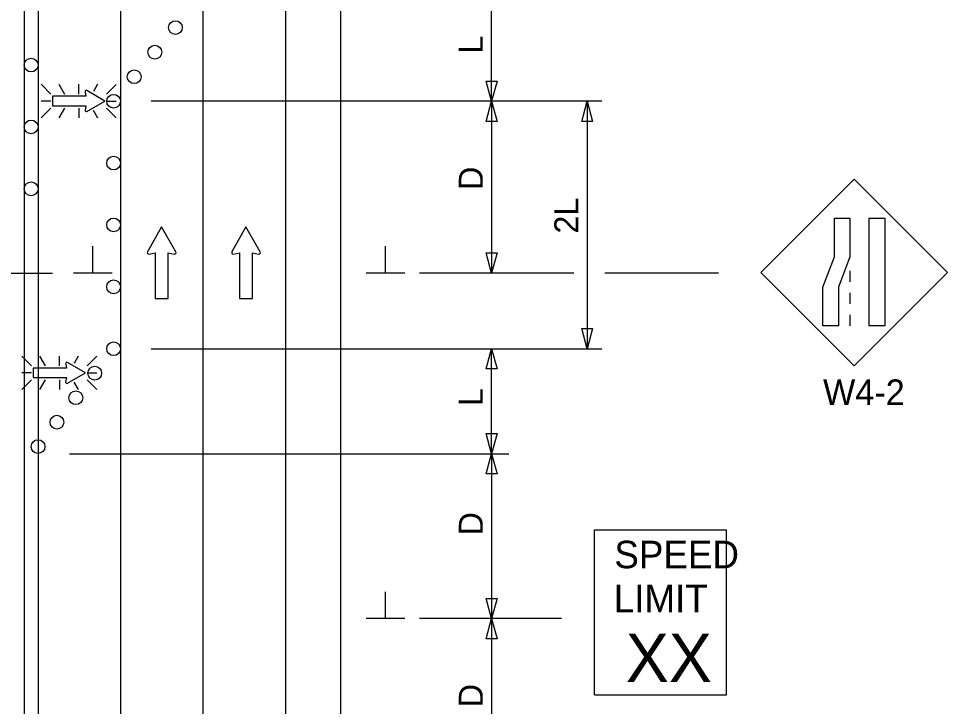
# Model space of a CAD drawing. Extents: x 16751 to 18475, y 5726 to 6923.
# Drawn here: x 17074.4 to 17344.7, y 6372.9 to 6573.1 of the extents above; entities that cross this region are included whole.
import ezdxf

# ---------------------------------------------------------------- set-up
doc = ezdxf.new("R2010")
doc.units = 0
for name, color, linetype in [('ALI_LEGAL_EX', 7, 'Continuous'), ('MT_SCRATCH_LEVEL_E', 7, 'Continuous'), ('PAVT_EDGE_EX', 7, 'Continuous'), ('TRAFFIC_SIGNS_PR', 7, 'Continuous'), ('TYPICAL_TEXT_DIMEN_PR', 7, 'Continuous')]:
    doc.layers.add(name, color=color, linetype=linetype)

msp = doc.modelspace()

# ---------------------------------------------------------------- linework, layer by layer
at = {"layer": 'ALI_LEGAL_EX'}
for p, q in [((17104.08, 6911.72), (17104.08, 6082.53)), ((17128.08, 6911.72), (17128.08, 6082.53)), ((17128.08, 6911.72), (17128.08, 6082.53))]:
    msp.add_line(p, q, dxfattribs=at)
for points in [[(17104.08, 6511.72), (17104.08, 6486.72)], [(17128.08, 6511.72), (17128.08, 6486.72)], [(17104.08, 6411.72), (17104.08, 6386.72)], [(17128.08, 6411.72), (17128.08, 6386.72)]]:
    msp.add_lwpolyline(points, dxfattribs=at)
at = {"layer": 'MT_SCRATCH_LEVEL_E'}
for p, q in [((17116.04, 6512.45), (17111.93, 6505.21)), ((17116.04, 6512.45), (17111.93, 6505.21)), ((17120.19, 6505.21), (17116.04, 6512.45)), ((17120.19, 6505.21), (17116.04, 6512.45)), ((17140.6, 6512.45), (17136.49, 6505.21)), ((17140.6, 6512.45), (17136.49, 6505.21)), ((17144.75, 6505.21), (17140.6, 6512.45)), ((17144.75, 6505.21), (17140.6, 6512.45)), ((17112.41, 6504.53), (17114.19, 6504.85)), ((17112.41, 6504.53), (17114.19, 6504.85)), ((17114.19, 6504.85), (17114.19, 6491.59)), ((17114.19, 6504.85), (17114.19, 6491.59)), ((17117.93, 6491.59), (17117.93, 6504.85)), ((17117.93, 6504.85), (17119.71, 6504.53)), ((17117.93, 6491.59), (17117.93, 6504.85)), ((17117.93, 6504.85), (17119.71, 6504.53)), ((17136.97, 6504.53), (17138.75, 6504.85)), ((17136.97, 6504.53), (17138.75, 6504.85)), ((17138.75, 6504.85), (17138.75, 6491.59)), ((17138.75, 6504.85), (17138.75, 6491.59)), ((17142.49, 6491.59), (17142.49, 6504.85)), ((17142.49, 6504.85), (17144.27, 6504.53)), ((17142.49, 6491.59), (17142.49, 6504.85)), ((17142.49, 6504.85), (17144.27, 6504.53)), ((17114.19, 6491.59), (17117.93, 6491.59)), ((17114.19, 6491.59), (17117.93, 6491.59)), ((17138.75, 6491.59), (17142.49, 6491.59)), ((17138.75, 6491.59), (17142.49, 6491.59))]:
    msp.add_line(p, q, dxfattribs=at)
for centre, start, end in [((17112.34, 6504.99), 150.4248, 279.9638), ((17112.34, 6504.99), 150.4248, 279.9638), ((17119.78, 6504.99), 260.0362, 29.7731), ((17119.78, 6504.99), 260.0362, 29.7731), ((17136.9, 6504.99), 150.4248, 279.9638), ((17136.9, 6504.99), 150.4248, 279.9638), ((17144.34, 6504.99), 260.0362, 29.7731), ((17144.34, 6504.99), 260.0362, 29.7731)]:
    msp.add_arc(centre, 0.463, start, end, dxfattribs=at)
at = {"layer": 'PAVT_EDGE_EX'}
for p, q in [((17076.08, 6911.72), (17076.08, 6082.53)), ((17080.08, 6911.72), (17080.08, 6082.53)), ((17152.08, 6911.72), (17152.08, 6082.53)), ((17168.08, 6911.72), (17168.08, 6082.53))]:
    msp.add_line(p, q, dxfattribs=at)
at = {"layer": 'TRAFFIC_SIGNS_PR'}
for p, q in [((17083.85, 6551.11), (17081.03, 6553.93)), ((17086.15, 6553.93), (17087.78, 6551.11)), ((17091.94, 6551.11), (17091.94, 6553.93)), ((17097.4, 6553.93), (17096.2, 6551.83)), ((17102.84, 6553.92), (17100.02, 6551.11)), ((17083.85, 6549.07), (17081.03, 6549.07)), ((17100.02, 6549.07), (17102.84, 6549.07)), ((17083.85, 6547.04), (17081.03, 6544.22)), ((17087.8, 6547.04), (17086.17, 6544.22)), ((17091.94, 6547.04), (17091.94, 6544.22)), ((17096.12, 6546.41), (17097.38, 6544.22)), ((17102.84, 6544.22), (17100.02, 6547.04)), ((17317.56, 6526.35), (17290.41, 6499.2)), ((17344.71, 6499.2), (17317.56, 6526.35)), ((17290.41, 6499.2), (17317.56, 6472.05)), ((17316.31, 6499.69), (17316.31, 6496.49)), ((17317.56, 6472.05), (17344.71, 6499.2)), ((17316.31, 6493.29), (17316.31, 6490.09)), ((17316.31, 6486.89), (17316.31, 6483.69)), ((17078.22, 6471.99), (17075.39, 6474.81)), ((17080.51, 6474.81), (17082.14, 6471.99)), ((17086.3, 6471.99), (17086.3, 6474.81)), ((17091.77, 6474.81), (17090.56, 6472.72)), ((17097.2, 6474.81), (17094.39, 6471.99)), ((17078.22, 6469.96), (17075.39, 6469.96)), ((17078.22, 6467.93), (17075.39, 6465.11)), ((17082.17, 6467.93), (17080.54, 6465.11)), ((17086.3, 6467.93), (17086.3, 6465.11)), ((17094.39, 6469.96), (17097.2, 6469.96)), ((17097.2, 6465.11), (17094.39, 6467.93)), ((17090.48, 6467.29), (17091.74, 6465.11)), ((17242.02, 6424.25), (17280.42, 6424.25)), ((17242.02, 6376.25), (17242.02, 6424.25)), ((17280.42, 6376.25), (17280.42, 6424.25)), ((17242.02, 6376.25), (17280.42, 6376.25))]:
    msp.add_line(p, q, dxfattribs=at)
for points in [[(17093.76, 6551.76), (17093.99, 6550.46), (17084.27, 6550.46), (17084.27, 6547.72), (17093.99, 6547.72), (17093.76, 6546.41)], [(17094.26, 6546.06), (17099.57, 6549.07), (17094.26, 6552.11)], [(17088.13, 6472.64), (17088.36, 6471.34), (17078.63, 6471.34), (17078.63, 6468.6), (17088.36, 6468.6), (17088.12, 6467.3)], [(17088.63, 6466.94), (17093.94, 6469.96), (17088.63, 6473)]]:
    msp.add_lwpolyline(points, dxfattribs=at)
for points in [[(17316.31, 6514.94), (17316.31, 6503.75), (17312.97, 6494.87), (17312.97, 6483.69), (17308.47, 6483.69), (17308.47, 6494.87), (17311.82, 6503.75), (17311.82, 6514.94)], [(17326.45, 6514.94), (17326.45, 6483.69), (17321.95, 6483.69), (17321.95, 6514.94)]]:
    msp.add_lwpolyline(points, close=True, dxfattribs=at)
for centre in [(17120.07, 6570.43), (17114.07, 6563.28), (17078.08, 6559.52), (17108.07, 6556.14), (17102.07, 6549), (17078.08, 6541.52), (17102.07, 6531), (17078.08, 6523.52), (17102.07, 6513), (17102.07, 6495), (17102.07, 6477), (17096.58, 6469.87), (17091.08, 6462.74), (17085.58, 6455.61), (17080.08, 6448.49)]:
    msp.add_circle(centre, 2, dxfattribs=at)
for centre, start, end in [((17094.1, 6551.82), 61.4833, 189.9593), ((17094.1, 6546.36), 170.7308, 298.8916), ((17088.46, 6472.7), 61.4833, 189.9593), ((17088.46, 6467.24), 170.7308, 298.8916)]:
    msp.add_arc(centre, 0.341, start, end, dxfattribs=at)
at = {"layer": 'TYPICAL_TEXT_DIMEN_PR'}
for p, q in [((17212.08, 6549), (17212.08, 6579.57)), ((17212.08, 6549), (17210.51, 6554.86)), ((17210.51, 6554.86), (17212.08, 6554.86)), ((17212.08, 6554.86), (17213.65, 6554.86)), ((17213.65, 6554.86), (17212.08, 6549)), ((17244.12, 6549), (17112.97, 6549)), ((17210.51, 6543.14), (17212.08, 6549)), ((17212.08, 6549), (17212.08, 6499)), ((17212.08, 6549), (17213.65, 6543.14)), ((17238.31, 6543.14), (17239.88, 6549)), ((17239.88, 6549), (17241.45, 6543.14)), ((17239.88, 6549), (17239.88, 6477)), ((17212.08, 6543.14), (17210.51, 6543.14)), ((17213.65, 6543.14), (17212.08, 6543.14)), ((17239.88, 6543.14), (17238.31, 6543.14)), ((17241.45, 6543.14), (17239.88, 6543.14)), ((17096, 6499), (17096, 6506.79)), ((17181.2, 6499), (17181.2, 6506.79)), ((17212.08, 6499), (17210.51, 6504.86)), ((17210.51, 6504.86), (17212.08, 6504.86)), ((17212.08, 6504.86), (17213.65, 6504.86)), ((17213.65, 6504.86), (17212.08, 6499)), ((17239.88, 6503.87), (17239.88, 6500.1)), ((16936.74, 6499), (17084.27, 6499)), ((17101.63, 6499), (17090.38, 6499)), ((17186.83, 6499), (17175.58, 6499)), ((17235.97, 6499), (17191.08, 6499)), ((17278.09, 6499), (17244.98, 6499)), ((17239.88, 6477), (17238.31, 6482.86)), ((17238.31, 6482.86), (17239.88, 6482.86)), ((17239.88, 6482.86), (17241.45, 6482.86)), ((17241.45, 6482.86), (17239.88, 6477)), ((17112.97, 6477), (17244.12, 6477)), ((17210.51, 6471.14), (17212.08, 6477)), ((17212.08, 6446.44), (17212.08, 6477)), ((17212.08, 6477), (17213.65, 6471.14)), ((17212.08, 6471.14), (17210.51, 6471.14)), ((17213.65, 6471.14), (17212.08, 6471.14)), ((17212.08, 6446.44), (17210.51, 6452.3)), ((17210.51, 6452.3), (17212.08, 6452.3)), ((17212.08, 6452.3), (17213.65, 6452.3)), ((17213.65, 6452.3), (17212.08, 6446.44)), ((17089.24, 6446.44), (17217.08, 6446.44)), ((17210.51, 6440.58), (17212.08, 6446.44)), ((17212.08, 6446.44), (17212.08, 6398.45)), ((17212.08, 6446.44), (17213.65, 6440.58)), ((17212.08, 6440.58), (17210.51, 6440.58)), ((17213.65, 6440.58), (17212.08, 6440.58)), ((17181.2, 6398.45), (17181.2, 6406.23)), ((17212.08, 6398.45), (17210.51, 6404.31)), ((17210.51, 6404.31), (17212.08, 6404.31)), ((17212.08, 6404.31), (17213.65, 6404.31)), ((17213.65, 6404.31), (17212.08, 6398.45)), ((17186.83, 6398.45), (17175.58, 6398.45)), ((17232.46, 6398.45), (17191.08, 6398.45)), ((17210.51, 6392.59), (17212.08, 6398.45)), ((17212.08, 6398.45), (17212.08, 6348.45)), ((17212.08, 6398.45), (17213.65, 6392.59)), ((17212.08, 6392.59), (17210.51, 6392.59)), ((17213.65, 6392.59), (17212.08, 6392.59))]:
    msp.add_line(p, q, dxfattribs=at)

# ---------------------------------------------------------------- texts
at = {"layer": 'TRAFFIC_SIGNS_PR'}
for s, height, p in [('W4-2', 7.44, (17308.52, 6460.61)), ('SPEED', 8, (17247.79, 6413.11)), ('LIMIT', 8, (17247.63, 6400.31)), ('XX', 14.031, (17251.13, 6380.01))]:
    msp.add_text(s, height=height, dxfattribs=at).set_placement(p)
at = {"layer": 'TYPICAL_TEXT_DIMEN_PR'}
for s, p in [('L', (17209.52, 6562.86)), ('D', (17209.52, 6523.22)), ('2L', (17237.32, 6510.51)), ('L', (17209.52, 6460.3)), ('D', (17209.52, 6422.67)), ('D', (17209.52, 6372.67))]:
    msp.add_text(s, height=7, rotation=90, dxfattribs=at).set_placement(p)

doc.saveas('drawing.dxf')
